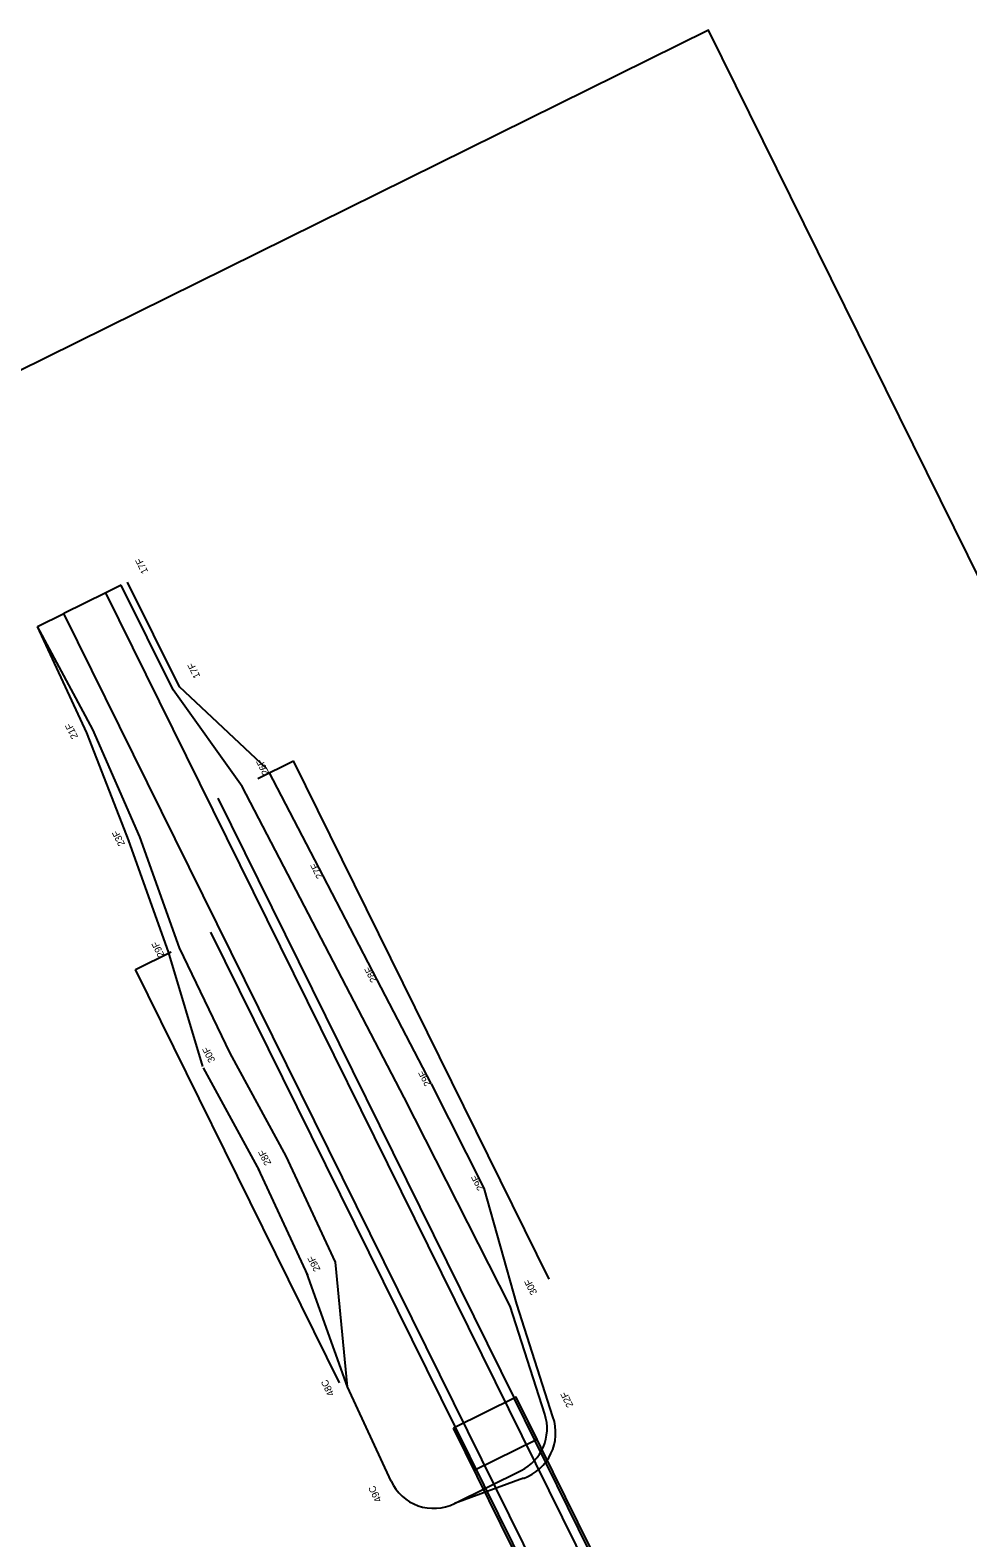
# Model space of a CAD drawing. Extents: x 2186914 to 2187984, y 1080077 to 1082015.
# Drawn here: x 2187216 to 2187617, y 1081371 to 1082015 of the extents above; entities that cross this region are included whole.
import ezdxf

# ---------------------------------------------------------------- set-up
doc = ezdxf.new("R2010")
doc.units = 0
for name, color, linetype in [('RD_PD_Bridge', 7, 'Continuous'), ('RD_PD_CstnLmt', 7, 'Continuous'), ('RD_PD_CstnLmt_TX', 7, 'Continuous'), ('RD_PD_DR_ErosCtrl', 7, 'Continuous'), ('RD_PD_Final_TrvlWay', 7, 'Continuous'), ('RD_PD_GR', 7, 'Continuous'), ('RD_PD_RW', 7, 'Continuous'), ('RD_Sketch2', 7, 'Continuous')]:
    doc.layers.add(name, color=color, linetype=linetype)

msp = doc.modelspace()

# ---------------------------------------------------------------- linework, layer by layer
at = {"layer": 'RD_PD_Bridge'}
for p, q in [((2187520.2, 1081233.28), (2187422.74, 1081430.51)), ((2187521.1, 1081233.72), (2187423.63, 1081430.95)), ((2187521.17, 1081233.76), (2187423.71, 1081430.99)), ((2187494.28, 1081220.47), (2187396.81, 1081417.7)), ((2187494.35, 1081220.5), (2187396.89, 1081417.74)), ((2187495.25, 1081220.95), (2187397.78, 1081418.18))]:
    msp.add_line(p, q, dxfattribs=at)
msp.add_lwpolyline([(2187396.81, 1081417.7), (2187405.67, 1081399.77), (2187432.57, 1081413.06), (2187423.71, 1081430.99)], close=True, dxfattribs=at)
at = {"layer": 'RD_PD_CstnLmt'}
for p, q in [((2187254.74, 1081778.05), (2187248.22, 1081774.83)), ((2187277.05, 1081733.3), (2187254.74, 1081778.05)), ((2187219.01, 1081760.39), (2187230.29, 1081765.97)), ((2187242.66, 1081716.31), (2187219.01, 1081760.39)), ((2187306.45, 1081692.06), (2187277.05, 1081733.3)), ((2187262.76, 1081670.47), (2187242.66, 1081716.31)), ((2187329.64, 1081647.75), (2187306.45, 1081692.06)), ((2187279.65, 1081623.04), (2187262.76, 1081670.47)), ((2187352.74, 1081603.39), (2187329.64, 1081647.75)), ((2187301.36, 1081578), (2187279.65, 1081623.04)), ((2187375.81, 1081559.02), (2187352.74, 1081603.39)), ((2187325.27, 1081534.05), (2187301.36, 1081578)), ((2187398.41, 1081514.42), (2187375.81, 1081559.02)), ((2187346.33, 1081488.68), (2187325.27, 1081534.05)), ((2187421.09, 1081469.85), (2187398.41, 1081514.42)), ((2187351.52, 1081435.47), (2187346.33, 1081488.68)), ((2187435.91, 1081423.68), (2187421.09, 1081469.85)), ((2187370.22, 1081395.09), (2187351.52, 1081435.47)), ((2187397.23, 1081385.56), (2187425.73, 1081399.64))]:
    msp.add_line(p, q, dxfattribs=at)
for centre, start, end in [((2187416.87, 1081417.57), 296.29665, 17.7992), ((2187388.37, 1081403.49), 204.8387, 296.29665)]:
    msp.add_arc(centre, 20, start, end, dxfattribs=at)
at = {"layer": 'RD_PD_DR_ErosCtrl'}
for p, q in [((2187279.74, 1081734.64), (2187257.42, 1081779.39)), ((2187240.01, 1081714.89), (2187219.01, 1081760.39)), ((2187317.04, 1081699.61), (2187279.74, 1081734.64)), ((2187258.18, 1081668.46), (2187240.01, 1081714.89)), ((2187341.16, 1081653.77), (2187317.97, 1081698.09)), ((2187274.94, 1081621.36), (2187258.05, 1081668.79)), ((2187364.27, 1081609.4), (2187341.17, 1081653.75)), ((2187289.65, 1081572.36), (2187274.94, 1081621.36)), ((2187387.35, 1081565.02), (2187364.27, 1081609.39)), ((2187313.85, 1081527.83), (2187289.94, 1081571.79)), ((2187410.01, 1081520.29), (2187387.41, 1081564.9)), ((2187334.53, 1081483.21), (2187313.48, 1081528.57)), ((2187423.95, 1081470.77), (2187410, 1081520.31)), ((2187351.52, 1081435.47), (2187334.17, 1081484.06)), ((2187439.4, 1081422.63), (2187423.95, 1081470.77)), ((2187426.74, 1081396.32), (2187397.23, 1081385.56))]:
    msp.add_line(p, q, dxfattribs=at)
msp.add_arc((2187419.81, 1081415.85), 20.73, 289.53097, 19.08885, dxfattribs=at)
at = {"layer": 'RD_PD_Final_TrvlWay'}
for p, q in [((2187248.22, 1081774.83), (2187230.29, 1081765.97)), ((2187606.1, 1081050.62), (2187248.22, 1081774.83)), ((2187588.16, 1081041.76), (2187230.29, 1081765.97))]:
    msp.add_line(p, q, dxfattribs=at)
at = {"layer": 'RD_PD_GR'}
for p, q in [((2187296.11, 1081686.95), (2187422.81, 1081430.55)), ((2187397.71, 1081418.14), (2187293.16, 1081629.72))]:
    msp.add_line(p, q, dxfattribs=at)
at = {"layer": 'RD_PD_RW'}
for p, q in [((2187313.14, 1081695.37), (2187328.38, 1081702.9)), ((2187437.81, 1081481.46), (2187328.38, 1081702.9)), ((2187260.88, 1081613.77), (2187276.12, 1081621.3)), ((2187348.16, 1081437.16), (2187260.88, 1081613.77))]:
    msp.add_line(p, q, dxfattribs=at)
at = {"layer": 'RD_Sketch2'}
msp.add_lwpolyline([(2187984.35, 1081047.02), (2187505.89, 1082015.25), (2186914.19, 1081722.86), (2187392.65, 1080754.62)], close=True, dxfattribs=at)

# ---------------------------------------------------------------- texts
at = {"layer": 'RD_PD_CstnLmt_TX'}
for s, p in [('17F', (2187266.39, 1081783.81)), ('17F', (2187288.71, 1081739.06)), ('21F', (2187236.38, 1081713.21)), ('26F', (2187318.11, 1081697.82)), ('23F', (2187256.48, 1081667.37)), ('27F', (2187341.29, 1081653.5)), ('29F', (2187273.37, 1081619.94)), ('28F', (2187364.39, 1081609.15)), ('30F', (2187295.08, 1081574.9)), ('29F', (2187387.47, 1081564.78)), ('28F', (2187319, 1081530.94)), ('29F', (2187410.07, 1081520.18)), ('29F', (2187340.05, 1081485.58)), ('30F', (2187432.74, 1081475.61)), ('48C', (2187346, 1081432.29)), ('22F', (2187448.2, 1081427.48)), ('49C', (2187366.26, 1081386.98))]:
    msp.add_text(s, height=3, rotation=116.29665, dxfattribs=at).set_placement(p)

doc.saveas('drawing.dxf')
